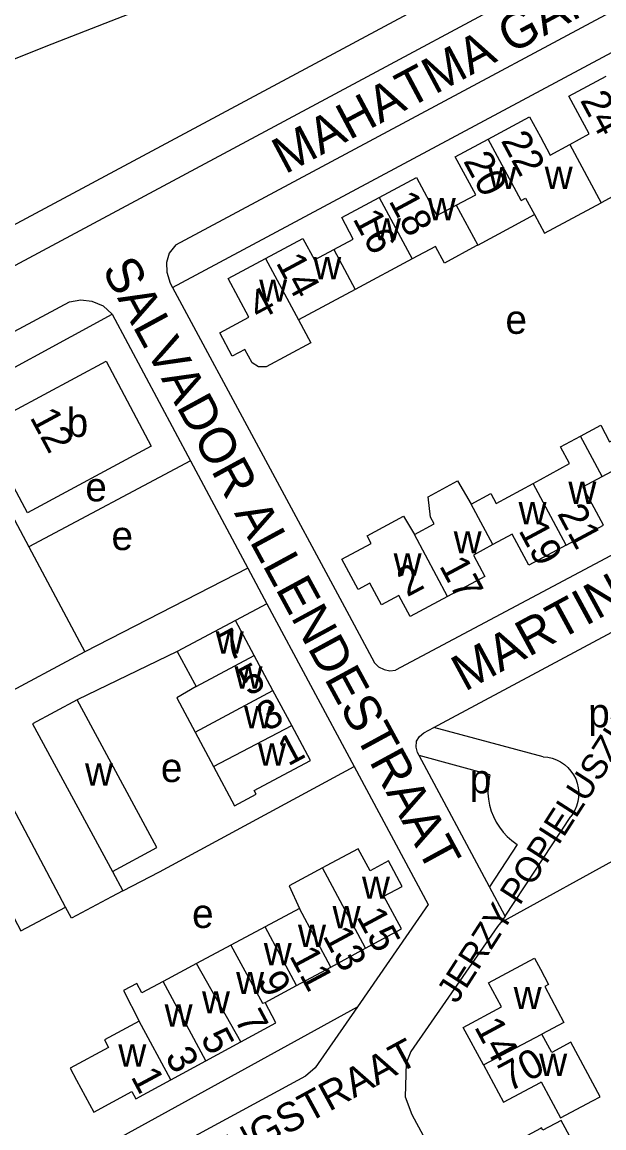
# Model space of a CAD drawing. Extents: x 157794 to 159375, y 380877 to 382306.
# Drawn here: x 158928.4 to 159008.8, y 381895.6 to 382048.3 of the extents above; entities that cross this region are included whole.
import ezdxf

# ---------------------------------------------------------------- set-up
doc = ezdxf.new("R2010")
doc.units = 0
for name, color, linetype in [('BLT_Basislijn', 7, 'Continuous'), ('BLT_Bebouwing', 7, 'Continuous'), ('BLT_Centroide', 7, 'Continuous'), ('BLT_Huisnummer', 7, 'Continuous'), ('BLT_Huisnummer_ tussenligend', 7, 'Continuous'), ('BLT_Onderverdeling_panden', 7, 'Continuous'), ('BLT_Straatnaam', 7, 'Continuous'), ('BLT_Straatnaam_verkleind', 7, 'Continuous')]:
    doc.layers.add(name, color=color, linetype=linetype)

msp = doc.modelspace()

# ---------------------------------------------------------------- linework, layer by layer
at = {"layer": 'BLT_Basislijn'}
for p, q in [((158918.66, 381995.96), (158929.37, 381975.87)), ((158951.68, 381987.76), (158929.37, 381975.87)), ((158929.37, 381975.87), (158937.08, 381961.39)), ((158959.61, 381972.95), (158937.08, 381961.39)), ((158959.61, 381972.95), (158962.24, 381968.03)), ((158962.24, 381968.03), (158957.88, 381965.69)), ((158962.24, 381968.03), (158974.28, 381945.55)), ((158937.08, 381961.39), (158920.45, 381952.52)), ((158949.86, 381961.41), (158936.04, 381954.76)), ((159000.36, 381946.89), (158985.3, 381950.95)), ((158993.02, 381944.38), (158983.26, 381947.07)), ((158974.28, 381945.55), (158984.49, 381926.48)), ((158995.14, 381924.9), (159004.18, 381938.63)), ((158996.79, 381934.79), (158992.99, 381928.91)), ((159014.08, 381934.75), (158994.51, 381923.94)), ((158940.89, 381931.03), (158942.35, 381928.36)), ((158984.49, 381926.48), (158974.73, 381912.35)), ((158994.51, 381923.94), (158994.07, 381923.44)), ((158995.14, 381924.9), (158994.51, 381923.94)), ((158929.15, 381887.3), (158974.73, 381912.35)), ((158974.73, 381912.35), (158968.91, 381903.93))]:
    msp.add_line(p, q, dxfattribs=at)
for points in [[(158861.64, 381979.44), (158865.56, 381981.52), (158907.88, 382004.25), (158914, 382007.54), (159056.77, 382084.07), (159059.38, 382085.5), (159091.58, 382102.75), (159097.42, 382106.14), (159103.19, 382109.67), (159112.65, 382115.73), (159125.89, 382124.38), (159127.38, 382125.43), (159145.8, 382138.15), (159163.12, 382150.91), (159179.42, 382163.47), (159183.59, 382166.45), (159186.15, 382168.04), (159188.85, 382169.38), (159189.71, 382169.79), (159191.99, 382170.85), (159192.34, 382170.99), (159195.08, 382172.13), (159196.82, 382172.94)], [(158872.47, 382014.55), (158874.39, 382016.74), (158876, 382018.39), (158878.28, 382020.48), (158881.01, 382022.61), (158883.71, 382024.38), (158886.62, 382025.98), (158886.91, 382026.11), (158895.95, 382030.32), (158914.54, 382038.11), (158931.77, 382045), (158986.2, 382066.29), (159004.58, 382073.57), (159022.64, 382081.6), (159039.22, 382090.22), (159053.65, 382098.28)], [(158864.15, 381986.44), (158905.51, 382008.66), (158911.63, 382011.95), (159054.39, 382088.46), (159056.99, 382089.9), (159057.98, 382090.42)], [(158949.67, 382017.58), (159042.84, 382067.52), (159044.41, 382067.5), (159045.94, 382066.86), (159047.44, 382065.95), (159048.45, 382064.86)], [(158949.21, 382011.67), (159048.45, 382064.86)], [(158949.67, 382017.58), (158948.75, 382016.44), (158948.37, 382015.15), (158948.4, 382013.83), (158948.87, 382012.3), (158949.21, 382011.67)], [(159075.55, 382014.49), (159075.98, 382013.3), (159076.07, 382011.86), (159075.82, 382010.47), (159074.85, 382009.29), (158980.01, 381958.86)], [(158949.21, 382011.67), (158973.57, 381966.4), (158977.08, 381959.87), (158977.62, 381959.33), (158978.43, 381958.96), (158979.21, 381958.78), (158980.01, 381958.86)], [(158863.6, 381968.11), (158863.59, 381969.44), (158863.99, 381970.67), (158864.6, 381971.64), (158865.39, 381972.37), (158869.33, 381974.46), (158911.67, 381997.21), (158917.78, 382000.49), (158934.96, 382009.7), (158936.52, 382010), (158938.07, 382009.81), (158939.64, 382009.15), (158940.85, 382007.99)], [(158918.66, 381995.96), (158940.85, 382007.99)], [(158940.85, 382007.99), (158951.68, 381987.76)], [(158951.68, 381987.76), (158959.61, 381972.95)], [(158985.3, 381950.95), (158986.46, 381951.58), (159015.1, 381966.91), (159015.78, 381966.9), (159016.44, 381966.71), (159017.03, 381966.33), (159017.48, 381965.88), (159029.46, 381943.09)], [(158983.26, 381947.07), (158983.04, 381947.48), (158982.82, 381948.2), (158982.91, 381949.03), (158983.28, 381949.71), (158983.92, 381950.21), (158985.3, 381950.95)], [(158992.99, 381928.91), (158983.26, 381947.07)], [(159000.36, 381946.89), (159001, 381946.83), (159001.62, 381946.69), (159002.22, 381946.47), (159002.79, 381946.18), (159003.32, 381945.82), (159003.8, 381945.4), (159004.22, 381944.92), (159004.58, 381944.4), (159004.87, 381943.83), (159005.08, 381943.23), (159005.23, 381942.6), (159005.29, 381941.97), (159005.27, 381941.33), (159005.17, 381940.7), (159004.99, 381940.09), (159004.74, 381939.5), (159004.42, 381938.95), (159004.18, 381938.63)], [(158942.35, 381928.36), (158947.39, 381931.02), (158974.28, 381945.55)], [(158993.02, 381944.38), (158992.86, 381943.55), (158992.77, 381942.72), (158992.76, 381941.88), (158992.83, 381941.04), (158992.98, 381940.21), (158993.21, 381939.4), (158993.51, 381938.62), (158993.89, 381937.87), (158994.34, 381937.16), (158994.85, 381936.49), (158995.42, 381935.88), (158996.05, 381935.32), (158996.79, 381934.79)], [(158994.07, 381923.44), (158982.1, 381906.19), (158981.46, 381904.6), (158981.34, 381899.92), (158982.25, 381897.5), (159026.42, 381815.66), (159028.37, 381813.47), (159029.25, 381813.04), (159032.7, 381813.07), (159049.22, 381822.15), (159051.23, 381824.01), (159053.32, 381826.75), (159067.69, 381869.91), (159066.93, 381871.95), (159061.42, 381882.67), (159029.46, 381943.09)], [(158942.35, 381928.36), (158940.76, 381927.53), (158935.24, 381924.62), (158934.42, 381926.13)], [(158995.14, 381924.9), (158992.99, 381928.91)], [(158968.91, 381903.93), (158967.57, 381902.79), (158917.68, 381875.79)]]:
    msp.add_lwpolyline(points, dxfattribs=at)
at = {"layer": 'BLT_Bebouwing'}
for p, q in [((158982.27, 382015.63), (158974.44, 382011.42)), ((158974.44, 382011.42), (158966.6, 382007.21)), ((158929.19, 381980.58), (158922.89, 381992.3)), ((158957.88, 381965.69), (158949.86, 381961.41)), ((158960.47, 381960.89), (158957.88, 381965.69)), ((158963.06, 381956.06), (158960.47, 381960.89)), ((158965.66, 381951.23), (158963.06, 381956.06)), ((158934.42, 381926.13), (158920.45, 381952.52)), ((158952.32, 381950.28), (158954.85, 381945.55)), ((158966.74, 381925.96), (158962.01, 381923.43)), ((158957.27, 381920.89), (158952.5, 381918.33)), ((158971.06, 381917.85), (158975.86, 381920.44)), ((158952.5, 381918.33), (158947.89, 381915.86)), ((158966.34, 381915.3), (158971.06, 381917.85)), ((158961.99, 381912.96), (158966.34, 381915.3)), ((158953.8, 381904.9), (158958.64, 381907.52)), ((158948.96, 381902.28), (158953.8, 381904.9))]:
    msp.add_line(p, q, dxfattribs=at)
for points in [[(159004.04, 382031.44), (159006.75, 382032.89), (159003.94, 382038.12), (159009.1, 382040.87)], [(158992.8, 382032.18), (158998.51, 382035.25), (159000, 382032.49), (159001.34, 382029.98), (159004.04, 382031.44)], [(159013.68, 382032.3), (159010.67, 382030.74), (159013.22, 382026), (159008.38, 382023.4)], [(158988.38, 382023.06), (158991.06, 382024.5), (158988.24, 382029.73), (158992.8, 382032.18)], [(158977.73, 382024.1), (158982.88, 382026.87), (158985.7, 382021.62), (158988.38, 382023.06)], [(158971.47, 382016.93), (158974.16, 382018.38), (158972.57, 382021.34), (158977.73, 382024.1)], [(158999.16, 382021.75), (159000.54, 382019.19), (159008.38, 382023.4)], [(158991.35, 382017.55), (158995.94, 382020.02), (158999.16, 382021.75)], [(158962.05, 382015.69), (158967.2, 382018.45), (158968.79, 382015.49), (158971.47, 382016.93)], [(158991.35, 382017.55), (158991.14, 382017.44), (158986.74, 382015.07), (158985.5, 382017.36), (158982.27, 382015.63)], [(158966.6, 382007.21), (158968.3, 382004.05), (158962.12, 382000.74), (158961.05, 382000.74), (158960.2, 382001.27), (158959.19, 382003.15), (158957.45, 382002.2), (158955.72, 382005.44), (158959.75, 382007.59), (158956.9, 382012.92), (158962.05, 382015.69)], [(158922.89, 381992.3), (158940.04, 382001.52), (158946.27, 381989.77), (158929.19, 381980.58)], [(159005.53, 381991.16), (159008.33, 381992.67), (159009.55, 381990.4), (159014.63, 381993.13)], [(158999, 381984.63), (159000, 381985.16), (159004.01, 381987.39), (159002.78, 381989.69), (159005.53, 381991.16)], [(159008.52, 381985.6), (159011.2, 381987.04), (159014.09, 381981.77), (159019.24, 381984.54)], [(158982.59, 381977.56), (158985.34, 381979.04), (158984.83, 381979.99), (158984.49, 381982.8), (158988.54, 381985.01), (158990.43, 381981.77)], [(159003.57, 381976.13), (159008.72, 381978.89), (159005.84, 381984.16), (159008.52, 381985.6)], [(158990.43, 381981.77), (158993.16, 381983.24), (158993.9, 381981.88), (158999, 381984.63)], [(158987.17, 381969.02), (158982.01, 381966.26), (158980.45, 381969.17), (158978.04, 381967.88), (158976.44, 381970.87), (158974.84, 381970.01), (158972.6, 381974.18), (158976.65, 381976.35), (158976.08, 381977.42), (158981.11, 381980.12), (158982.59, 381977.56)], [(159003.57, 381976.13), (158998.42, 381973.36), (158996.12, 381977.63), (158993.43, 381976.18)], [(158993.43, 381976.18), (158990.74, 381974.74), (158992.33, 381971.79), (158987.17, 381969.02)], [(158949.86, 381961.41), (158952.23, 381957.01), (158952.46, 381956.58)], [(158952.46, 381956.58), (158949.78, 381955.01), (158952.32, 381950.28)], [(158936.04, 381954.76), (158929.87, 381951.43), (158940.89, 381931.03)], [(158940.89, 381931.03), (158947.04, 381934.34), (158936.04, 381954.76)], [(158954.85, 381945.55), (158957.77, 381940.11), (158960.77, 381941.72), (158960.49, 381942.23), (158963.85, 381944.03), (158968.26, 381946.39), (158965.66, 381951.23)], [(158914.38, 381949.07), (158928.26, 381922.86), (158934.42, 381926.13)], [(158975.86, 381920.44), (158980.8, 381923.11), (158978.37, 381927.62), (158980.92, 381928.98), (158979.04, 381932.5), (158976.47, 381931.13), (158974.82, 381934.2), (158970.42, 381931.82), (158969.92, 381931.55)], [(158969.92, 381931.55), (158965.3, 381929.06), (158966.74, 381925.96)], [(158962.01, 381923.43), (158957.27, 381920.89)], [(158992.13, 381904.34), (158989.35, 381909.49), (158994.63, 381912.34), (158992.84, 381915.68), (158999.17, 381919.09), (159000, 381917.55), (159001.12, 381915.46), (159000.59, 381915.17), (159003.25, 381910.22), (159000.21, 381908.58)], [(158947.89, 381915.86), (158944.95, 381914.29), (158944.26, 381915.59), (158942.43, 381914.61), (158944.59, 381910.37)], [(158958.64, 381907.52), (158963.48, 381910.14), (158961.99, 381912.96)], [(158944.59, 381910.37), (158939.79, 381907.81), (158940.36, 381906.74)], [(158992.13, 381904.34), (158994.91, 381899.18), (159000, 381901.93), (159000.11, 381901.99), (159002.79, 381897.02), (159007.19, 381899.39), (159008.23, 381899.95), (159004.19, 381907.47), (159001.57, 381906.06), (159000.21, 381908.58)], [(158940.36, 381906.74), (158935.09, 381903.9), (158935.96, 381902.22), (158938.33, 381897.81), (158943.59, 381900.65)], [(158943.59, 381900.65), (158944.12, 381899.67), (158948.96, 381902.28)], [(159005.43, 381891.93), (159002.88, 381896.68), (159000.33, 381895.31), (159000.16, 381895.63), (159000, 381895.55), (158996.43, 381893.61), (158992.03, 381891.23), (158994.8, 381886.06)]]:
    msp.add_lwpolyline(points, dxfattribs=at)
at = {"layer": 'BLT_Onderverdeling_panden'}
for p, q in [((158997.36, 382023.7), (158992.8, 382032.18)), ((159004.04, 382031.44), (159008.38, 382023.4)), ((158977.73, 382024.1), (158982.27, 382015.63)), ((158988.38, 382023.06), (158991.35, 382017.55)), ((158971.47, 382016.93), (158974.44, 382011.42)), ((158962.05, 382015.69), (158966.6, 382007.21)), ((159008.52, 381985.6), (159005.53, 381991.16)), ((159003.57, 381976.13), (158999, 381984.63)), ((158993.43, 381976.18), (158990.43, 381981.77)), ((158987.17, 381969.02), (158982.59, 381977.56)), ((158952.46, 381956.58), (158960.47, 381960.89)), ((158952.32, 381950.28), (158963.06, 381956.06)), ((158954.85, 381945.55), (158965.66, 381951.23)), ((158975.86, 381920.44), (158969.92, 381931.55)), ((158971.06, 381917.85), (158966.74, 381925.96)), ((158966.34, 381915.3), (158962.01, 381923.43)), ((158958.64, 381907.52), (158952.5, 381918.33)), ((158953.8, 381904.9), (158947.89, 381915.86)), ((158948.96, 381902.28), (158944.59, 381910.37)), ((158992.13, 381904.34), (159000.21, 381908.58))]:
    msp.add_line(p, q, dxfattribs=at)
for points in [[(158997.36, 382023.7), (158997.94, 382024.02), (158999.16, 382021.75)], [(158957.27, 381920.89), (158961.61, 381912.88), (158961.99, 381912.96)]]:
    msp.add_lwpolyline(points, dxfattribs=at)

# ---------------------------------------------------------------- texts
at = {"layer": 'BLT_Centroide'}
for s, p in [('w', (158992.8, 382025.27)), ('w', (159000.59, 382025.3)), ('w', (158984.45, 382020.97)), ('w', (158976.88, 382018.19)), ('w', (158968.63, 382012.84)), ('w', (158961.16, 382009.72)), ('e', (158995.17, 382005.29)), ('b', (158934.58, 381991.06)), ('e', (158937.16, 381982.16)), ('w', (159003.86, 381981.8)), ('w', (158996.98, 381979)), ('e', (158940.77, 381975.43)), ('w', (158988.02, 381974.97)), ('w', (158979.73, 381971.91)), ('w', (158955.17, 381961.12)), ('w', (158957.76, 381956.31)), ('w', (158959.07, 381950.81)), ('p', (159006.6, 381950.96)), ('w', (158961, 381945.66)), ('w', (158937.12, 381942.91)), ('e', (158947.59, 381943.4)), ('p', (158990.24, 381941.84)), ('w', (158975.36, 381927.28)), ('e', (158951.9, 381923.25)), ('w', (158971.3, 381923.19)), ('w', (158966.53, 381920.62)), ('w', (158961.8, 381918.11)), ('w', (158957.98, 381914.11)), ('w', (158996.3, 381912.05)), ('w', (158953.27, 381911.45)), ('w', (158948.11, 381909.64)), ('w', (158941.72, 381904.09)), ('w', (158999.83, 381902.81))]:
    msp.add_text(s, height=4, dxfattribs=at).set_placement(p)
at = {"layer": 'BLT_Huisnummer'}
for s, rotation, p in [('22', 298.2475, (158994.48, 382031.98)), ('18', 298.2475, (158978.99, 382023.67)), ('14', 298.2475, (158963.41, 382015.14)), ('4', 28.261, (158961.08, 382007.06)), ('12', 298.2475, (158929.43, 381993.78)), ('21', 298.1914, (159002.25, 381980.49)), ('17', 298.1914, (158985.96, 381973.28)), ('2', 28.1943, (158981.59, 381968.89)), ('7', 28.1595, (158956.93, 381959.95)), ('1', 28.1595, (158965.15, 381945.53)), ('15', 298.1844, (158974.53, 381924.82)), ('13', 298.1844, (158969.87, 381922.17)), ('9', 298.1844, (158960.85, 381916)), ('14', 298.3346, (158990.79, 381909.6)), ('5', 298.1844, (158953, 381908.07)), ('70', 28.2847, (158995.66, 381900.55)), ('1', 298.1844, (158943.37, 381902.72))]:
    msp.add_text(s, height=4, rotation=rotation, dxfattribs=at).set_placement(p)
at = {"layer": 'BLT_Huisnummer_ tussenligend'}
for s, rotation, p in [('24', 298.2475, (159005.42, 382037.55)), ('20', 298.2475, (158989.29, 382029.16)), ('16', 298.2475, (158974.02, 382021.2)), ('19', 298.1914, (158996.91, 381978.16)), ('5', 28.1595, (158959.7, 381955.19)), ('3', 28.1595, (158962.23, 381950.32)), ('11', 298.1844, (158965.26, 381919.43)), ('7', 298.1844, (158957.68, 381910.67)), ('3', 298.1844, (158948.1, 381905.53))]:
    msp.add_text(s, height=4, rotation=rotation, dxfattribs=at).set_placement(p)
at = {"layer": 'BLT_Straatnaam'}
for s, rotation, p in [('MAHATMA GANDHILAAN', 28.0837, (158964.75, 382027.28)), ('SALVADOR ALLENDESTRAAT', 298.5304, (158939.38, 382014.17)), ('MARTIN LUTHER KINGSTRAAT', 28.5304, (158989.55, 381955.84))]:
    msp.add_text(s, height=5, rotation=rotation, dxfattribs=at).set_placement(p)
at = {"layer": 'BLT_Straatnaam_verkleind'}
for s, height, rotation, p in [('JERZY POPIELUSZKOPLANTSOEN', 3.5, 57.2579, (158988.42, 381912.68)), ('MARTIN LUTHER KINGSTRAAT', 4, 28.5304, (158913.91, 381866.91))]:
    msp.add_text(s, height=height, rotation=rotation, dxfattribs=at).set_placement(p)

doc.saveas('drawing.dxf')
